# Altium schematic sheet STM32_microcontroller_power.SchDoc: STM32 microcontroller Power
size A4; Date: Not used; ApprovedBy: Not used; CheckedBy: Not used; Author: Not used; CompanyName: STMicroelectronics; DrawnBy: Not used; Engineer: Not used; Organization: Not used; Address1: Not used; Address2: Not used; Address3: Not used; Address4: Not used; DocumentNumber: 4; Revision: Not used; SheetNumber: 4; SheetTotal: 8
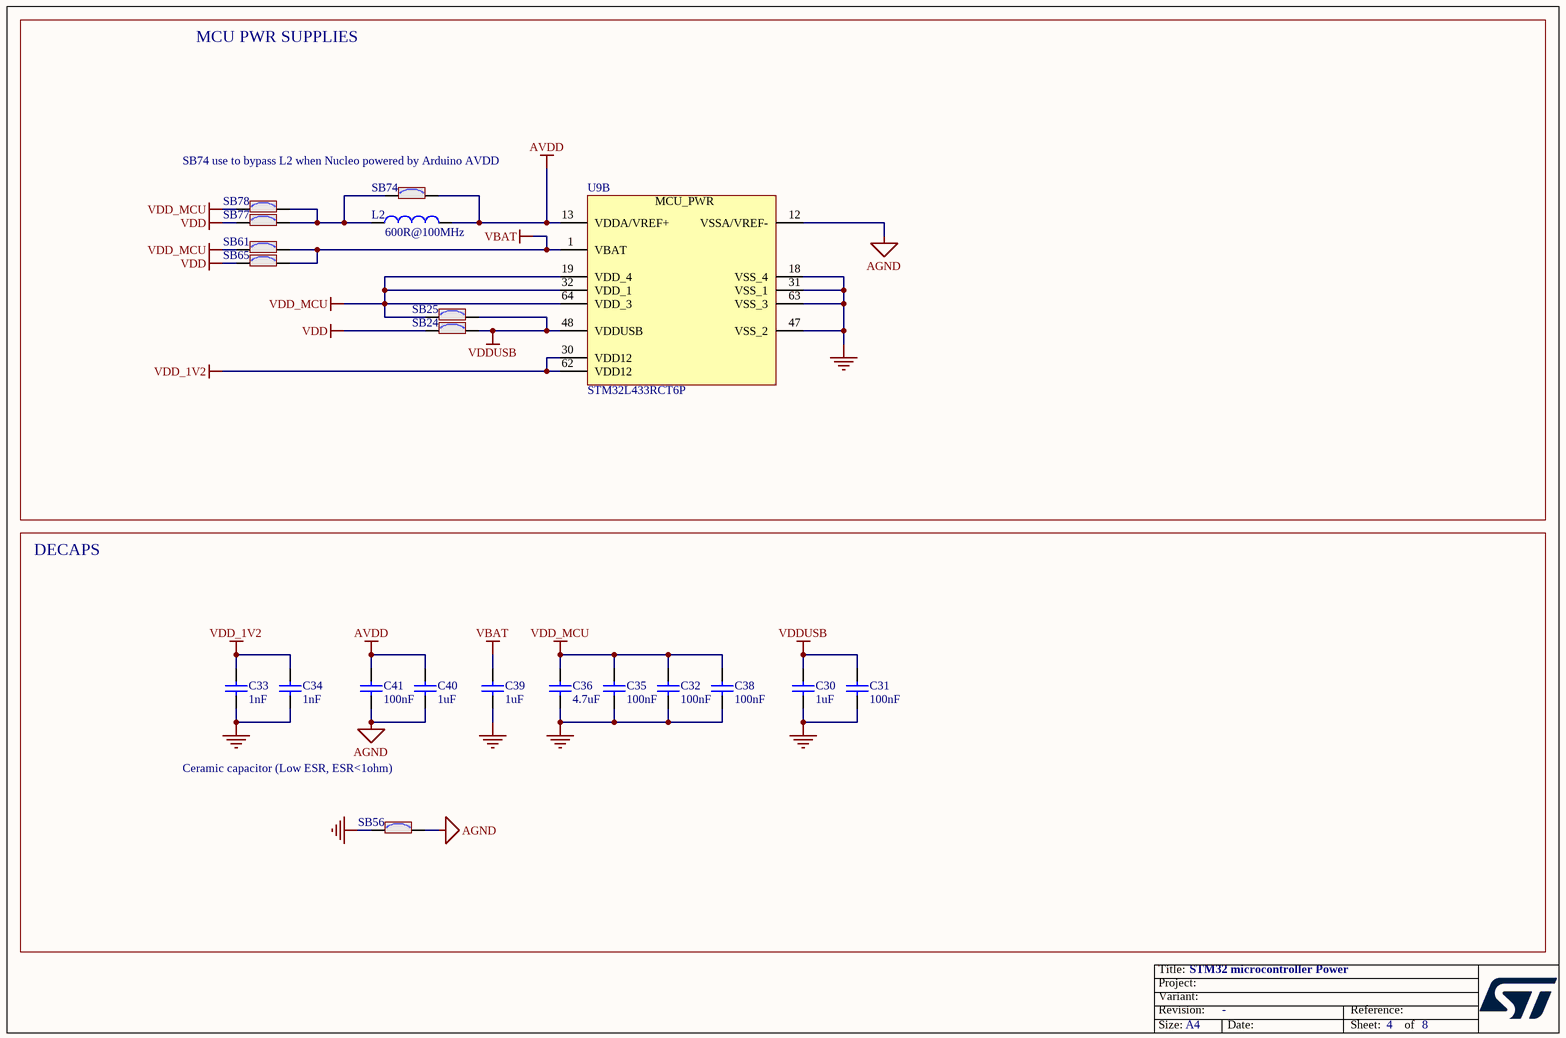
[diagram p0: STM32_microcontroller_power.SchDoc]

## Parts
C30  value 1uF  [C0603]  (hidden comment: Capacitor)
C31  value 100nF  [C0603]  (hidden comment: Capacitor)
C32  value 100nF  [C0603]  (hidden comment: Capacitor)
C33  value 1nF  [C0603]  (hidden comment: Capacitor)
C34  value 1nF  [C0603]  (hidden comment: Capacitor)
C35  value 100nF  [C0603]  (hidden comment: Capacitor)
C36  value 4.7uF  [C0603]  (hidden comment: Capacitor)
C38  value 100nF  [C0603]  (hidden comment: Capacitor)
C39  value 1uF  [C0603]  (hidden comment: Capacitor)
C40  value 1uF  [C0603]  (hidden comment: Capacitor)
C41  value 100nF  [C0603]  (hidden comment: Capacitor)
L2  value 600R@100MHz  [L0603]  (hidden comment: BEAD)
SB24  SB_ON  [SOLDER-BRIDGE_R0603-0R]  (value not drawn)
SB25  SB_ON  [SOLDER-BRIDGE_R0603-0R]  (value not drawn)
SB56  SB_ON  [SOLDER-BRIDGE_R0603-0R]  (value not drawn)
SB61  SB_ON  [SOLDER-BRIDGE_R0603-0R]  (value not drawn)
SB65  SB_ON  [SOLDER-BRIDGE_R0603-0R]  (value not drawn)
SB74  SB_ON  [SOLDER-BRIDGE_R0603-0R]  (value not drawn)
SB77  SB_ON  [SOLDER-BRIDGE_R0603-0R]  (value not drawn)
SB78  SB_ON  [SOLDER-BRIDGE_R0603-0R]  (value not drawn)
U9  STM32L433RCT6P  [ICC_LQFP64_10X10_P050_SOCKET_YAMAICHI_IC149-064-069-B5_NM]  (part B of 2)

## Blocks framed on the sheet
MCU PWR SUPPLIES: L2 SB24 SB25 SB61 SB65 SB74 SB77 SB78 U9
DECAPS: C30-C36 C38-C41 SB56

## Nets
AGND: C40.2 C41.1 SB56.2 U9.12(VSSA/VREF-)
AVDD: C40.1 C41.2 L2.2 SB74.2 U9.13(VDDA/VREF+)
GND: C30.2 C31.1 C32.1 C33.1 C34.1 C35.1 C36.1 C38.1 C39.2 SB56.1 U9.18(VSS_4) U9.31(VSS_1) U9.47(VSS_2) U9.63(VSS_3)
VBAT: C39.1 SB61.1 SB65.1 U9.1(VBAT)
VDD: SB24.1 SB65.2 SB77.1
VDD_1V2: C33.2 C34.2 U9.30(VDD12) U9.62(VDD12)
VDD_MCU: C32.2 C35.2 C36.2 C38.2 SB25.1 SB61.2 SB78.1 U9.19(VDD_4) U9.32(VDD_1) U9.64(VDD_3)
VDDUSB: C30.1 C31.2 SB24.2 SB25.2 U9.48(VDDUSB)
NetL2_1: L2.1 SB74.1 SB77.2 SB78.2

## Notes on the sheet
- SB74 use to bypass L2 when Nucleo powered by Arduino AVDD
- Ceramic capacitor (Low ESR, ESR<1ohm)

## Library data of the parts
C30 C39 C40 = MCD-00238: Capacitor, MLCC, 1uF, 6V3, X5R, +/-10%, 0603, T=0,8mm; Manufacturer_Part_Number: CC0603KRX5R5BB105; Manufacturer: YAGEO; Part_Preference: Recommended
C31 C32 C35 C38 C41 = MCD-00237: Capacitor, MLCC, 100nF, 6V3, X5R, +/-10%, 0603, T=0.8mm; Part_Preference: Not recommended; Manufacturer: YAGEO; Manufacturer_Part_Number: CC0603KRX5R5BB104; Component_Country_Of_Origin: China; ShowFields: YES; ID: 2631
C33 C34 = MCD-00273: Capacitor, MLCC, 1nF, 16V, X7R, +/-10%, 0603, T=0,8mm; Manufacturer_Part_Number: CC0603KRX7R7BB102; Manufacturer: YAGEO; Part_Preference: Recommended
C36 = MCD-00009: Capacitor, MLCC, 4.7uF, 16V, X5R, +/-10%, 0603, T=0.8mm; Manufacturer_Part_Number: CC0603KRX5R7BB475; Manufacturer: YAGEO; Part_Preference: Recommended
L2 = MCD-00047: SMD Chip ferrite bead, 600R@100MHz +/-25%, 350mA, 500mohm DC, 0603, T=0.8mm; Part_Type: Inductor; Manufacturer_Part_Number: FCM1608KF-601T03; Manufacturer: TAI-TECH; Part_Preference: Recommended
SB24 SB25 SB56 SB61 SB65 SB74 SB77 SB78 = MCD-00071: Solder Bridge ON; Part_Type: Misc; Part_Preference: Recommended; Manufacturer: YAGEO; Manufacturer_Part_Number: RC0603JR-070RL
U9 = MCD-00548: STM32L433RCT6P: External SMPS configuration. LQFP64 package; Part_Type: IC; Manufacturer: STMICROELECTRONICS; BMS_Part_Number: 9175261; Part_Preference: Recommended; Manufacturer_HQ_COO: EU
